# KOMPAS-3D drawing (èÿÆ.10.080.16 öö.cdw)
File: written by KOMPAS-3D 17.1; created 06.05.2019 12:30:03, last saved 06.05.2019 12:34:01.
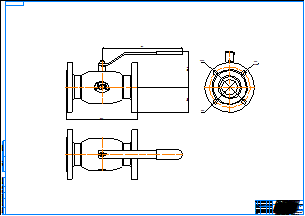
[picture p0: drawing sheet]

Sheet 1: A0, landscape

Title block, sheet 1: name: КШТ.10.080.16 ФФ; material: Внимание! Данный продукт является объектом авторского права ООО «Торговый Дом АДЛ». / Запрещается изменение, копирование, распространение / (в том числе путем копирования на другие сайты и ресурсы в Интернете) / или любое иное использование информации и объектов без предварительного / согласия правообладателя (ООО «Торговый Дом АДЛ»).; sheets: 1; organisation: ООО "Торговый дом АДЛ"; sheet format: A0; stored path: C:\Users\tra\Desktop\2д чертежи\Шаровые краны БИВАЛ\КШ_Бивал_серия_10\KOMPAS 2D\КШТ.10.080.16 ФФ.cdw

Views: Вид 1, Проекционный вид 2, Проекционный вид 3
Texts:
  user
Dimensions and other numbers on the sheet: 280; 316; 138,5; 97,5; 160; 63; 18; 4 Отв.; 1:1; 1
